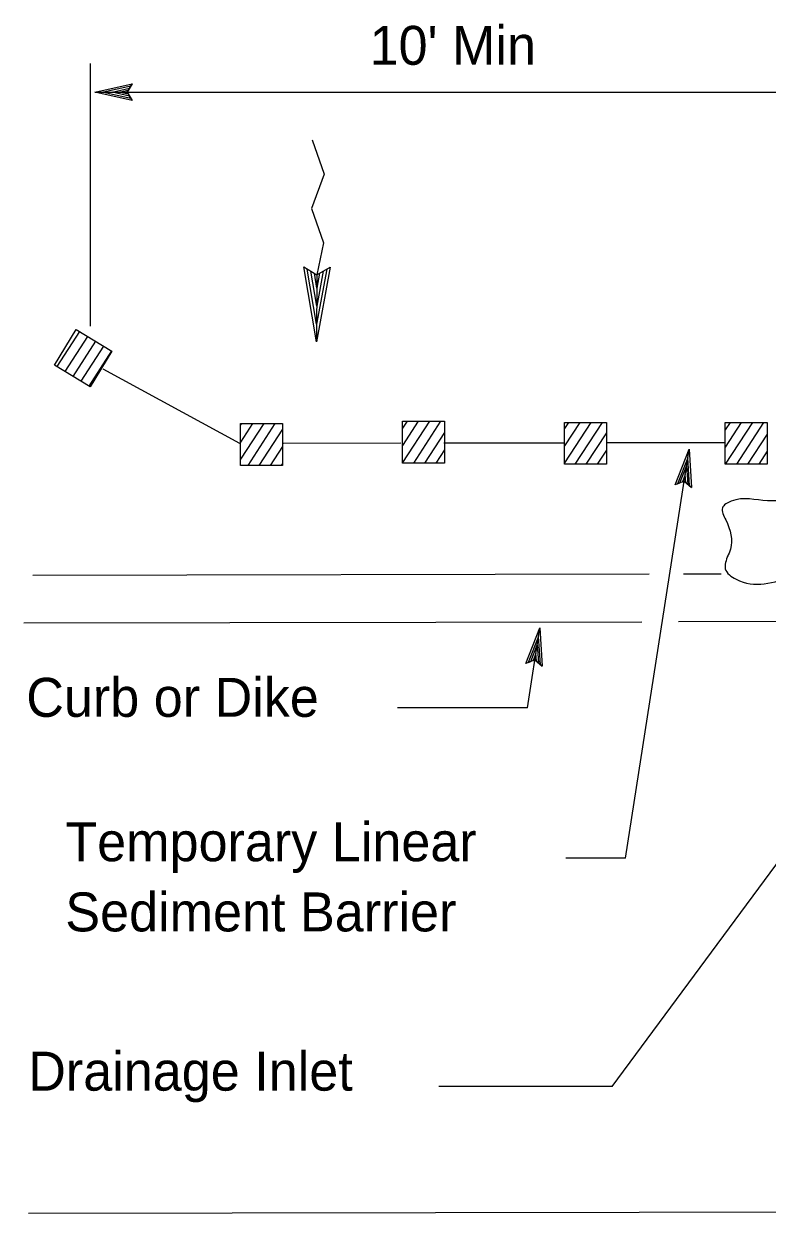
# Model space of a CAD drawing. Extents: x 6708945 to 6710368, y 1871409 to 1872338.
# Drawn here: x 6709577.4 to 6709691.9, y 1871532.3 to 1871715.4 of the extents above; entities that cross this region are included whole.
import ezdxf

# ---------------------------------------------------------------- set-up
doc = ezdxf.new("R2010")
doc.units = 0
for name, color, linetype in [('1 Control', 7, 'Continuous'), ('57 Undefined', 7, 'Continuous'), ('60 Nongeo Data', 7, 'Continuous'), ('63 Undefined', 7, 'Continuous')]:
    doc.layers.add(name, color=color, linetype=linetype)

msp = doc.modelspace()

# ---------------------------------------------------------------- linework, layer by layer
at = {"layer": '1 Control'}
for p, q in [((6709586, 1871668.01), (6709582.49, 1871662.61)), ((6709587.23, 1871667.27), (6709583.72, 1871661.86)), ((6709588.46, 1871666.52), (6709584.95, 1871661.12)), ((6709589.69, 1871665.77), (6709586.18, 1871660.37)), ((6709590.92, 1871665.03), (6709587.42, 1871659.62)), ((6709614.35, 1871653.84), (6709610.79, 1871648.35)), ((6709612.63, 1871653.84), (6709610.79, 1871650.99)), ((6709610.92, 1871653.84), (6709610.79, 1871653.64)), ((6709616.07, 1871653.84), (6709611.89, 1871647.4)), ((6709639.86, 1871654.22), (6709635.72, 1871647.85)), ((6709638.14, 1871654.22), (6709635.72, 1871650.5)), ((6709636.43, 1871654.22), (6709635.72, 1871653.14)), ((6709641.58, 1871654.22), (6709637.4, 1871647.78)), ((6709664.71, 1871654.03), (6709660.66, 1871647.8)), ((6709662.99, 1871654.03), (6709660.66, 1871650.44)), ((6709661.28, 1871654.03), (6709660.66, 1871653.09)), ((6709666.43, 1871654.03), (6709662.25, 1871647.59)), ((6709689.59, 1871654.03), (6709685.41, 1871647.6)), ((6709687.87, 1871654.03), (6709685.41, 1871650.24)), ((6709686.16, 1871654.03), (6709685.41, 1871652.89)), ((6709691.31, 1871654.03), (6709687.12, 1871647.59)), ((6709617.22, 1871652.97), (6709613.6, 1871647.4)), ((6709642.16, 1871652.47), (6709639.11, 1871647.78)), ((6709667.1, 1871652.42), (6709663.96, 1871647.59)), ((6709691.85, 1871652.22), (6709688.84, 1871647.59)), ((6709617.22, 1871650.33), (6709615.32, 1871647.4)), ((6709642.16, 1871649.83), (6709640.83, 1871647.78)), ((6709667.1, 1871649.78), (6709665.68, 1871647.59)), ((6709691.85, 1871649.58), (6709690.56, 1871647.59)), ((6709617.22, 1871647.69), (6709617.04, 1871647.4))]:
    msp.add_line(p, q, dxfattribs=at)
for points in [[(6709585.47, 1871668.33), (6709590.98, 1871664.99), (6709587.64, 1871659.49), (6709582.14, 1871662.83)], [(6709610.79, 1871653.84), (6709617.22, 1871653.84), (6709617.22, 1871647.4), (6709610.79, 1871647.4)], [(6709635.72, 1871654.22), (6709642.16, 1871654.22), (6709642.16, 1871647.78), (6709635.72, 1871647.78)], [(6709660.66, 1871654.03), (6709667.1, 1871654.03), (6709667.1, 1871647.59), (6709660.66, 1871647.59)], [(6709685.41, 1871654.03), (6709691.85, 1871654.03), (6709691.85, 1871647.59), (6709685.41, 1871647.59)]]:
    msp.add_lwpolyline(points, close=True, dxfattribs=at)
at = {"layer": '57 Undefined'}
for p, q in [((6709587.7, 1871668.85), (6709587.7, 1871709.29)), ((6709588.34, 1871704.86), (6709715.63, 1871704.86)), ((6709670.02, 1871586.95), (6709679.85, 1871649.92)), ((6709654.95, 1871610.12), (6709656.87, 1871622.41)), ((6709654.95, 1871610.12), (6709634.94, 1871610.12)), ((6709668.01, 1871551.82), (6709699.53, 1871594.51)), ((6709670.02, 1871586.95), (6709660.85, 1871586.95)), ((6709668.01, 1871551.82), (6709641.29, 1871551.82))]:
    msp.add_line(p, q, dxfattribs=at)
at = {"layer": '60 Nongeo Data'}
for p, q in [((6709594.1, 1871706.14), (6709594.1, 1871706.14)), ((6709588.34, 1871704.86), (6709588.34, 1871704.86)), ((6709594.1, 1871703.58), (6709594.1, 1871703.58)), ((6709679.85, 1871649.92), (6709679.85, 1871649.92)), ((6709677.69, 1871644.43), (6709677.69, 1871644.43)), ((6709680.22, 1871644.03), (6709680.22, 1871644.03)), ((6709656.87, 1871622.41), (6709656.87, 1871622.41)), ((6709654.71, 1871616.91), (6709654.71, 1871616.91)), ((6709657.24, 1871616.52), (6709657.24, 1871616.52))]:
    msp.add_line(p, q, dxfattribs=at)
for points in [[(6709594.1, 1871703.58), (6709588.34, 1871704.86), (6709594.1, 1871706.14), (6709593.9, 1871705.8), (6709589.68, 1871704.87), (6709593.9, 1871703.92), (6709593.7, 1871704.26), (6709591, 1871704.86), (6709593.69, 1871705.46), (6709593.49, 1871705.12), (6709592.32, 1871704.86), (6709593.49, 1871704.6), (6709593.34, 1871704.86), (6709594.1, 1871706.14), (6709593.34, 1871704.86)], [(6709677.69, 1871644.43), (6709679.85, 1871649.92), (6709680.22, 1871644.03), (6709679.92, 1871644.29), (6709679.65, 1871648.6), (6709678.06, 1871644.58), (6709678.43, 1871644.73), (6709679.44, 1871647.3), (6709679.62, 1871644.54), (6709679.31, 1871644.8), (6709679.23, 1871645.99), (6709678.8, 1871644.88), (6709679.08, 1871644.99), (6709680.22, 1871644.03), (6709679.08, 1871644.99)], [(6709654.71, 1871616.91), (6709656.87, 1871622.41), (6709657.24, 1871616.52), (6709656.94, 1871616.77), (6709656.67, 1871621.09), (6709655.08, 1871617.06), (6709655.45, 1871617.21), (6709656.46, 1871619.79), (6709656.63, 1871617.03), (6709656.33, 1871617.28), (6709656.25, 1871618.48), (6709655.82, 1871617.36), (6709656.1, 1871617.47), (6709657.24, 1871616.52), (6709656.1, 1871617.47)]]:
    msp.add_lwpolyline(points, close=True, dxfattribs=at)
for points in [[(6709589.56, 1871662.27), (6709610.62, 1871650.83)], [(6709617.38, 1871650.84), (6709635.47, 1871650.87)], [(6709642.09, 1871650.88), (6709660.59, 1871650.91)], [(6709667.08, 1871650.92), (6709685.38, 1871650.95)], [(6709578.82, 1871630.54), (6709673.67, 1871630.7)], [(6709678.95, 1871630.71), (6709684.77, 1871630.72)], [(6709577.41, 1871623.19), (6709672.55, 1871623.35)], [(6709678.2, 1871623.36), (6709932.4, 1871623.77)], [(6709578.14, 1871532.3), (6710048.25, 1871533.08)]]:
    msp.add_lwpolyline(points, dxfattribs=at)
msp.add_spline([(6709685.81, 1871633.55), (6709685.41, 1871631.49), (6709687.07, 1871629.88), (6709695.81, 1871630.27), (6709699.39, 1871631.08), (6709704.17, 1871630.12), (6709708.12, 1871629.94), (6709708.74, 1871631.23), (6709709.2, 1871640.9), (6709707.25, 1871644.03), (6709703.6, 1871644.06), (6709697.36, 1871642.67), (6709691.88, 1871641.95), (6709686.33, 1871641.92), (6709684.96, 1871640.86), (6709685.47, 1871639.03), (6709686.2, 1871634.53), (6709685.73, 1871633.32)], degree=3, dxfattribs=at)
at = {"layer": '63 Undefined'}
for p, q in [((6709622.46, 1871666.41), (6709620.53, 1871677.97)), ((6709620.53, 1871677.97), (6709622.55, 1871676.77)), ((6709622.48, 1871669.17), (6709621.06, 1871677.64)), ((6709624.6, 1871677.93), (6709622.46, 1871666.41)), ((6709624.06, 1871677.62), (6709622.48, 1871669.17)), ((6709622.55, 1871676.77), (6709624.6, 1871677.93)), ((6709622.51, 1871671.9), (6709621.61, 1871677.32)), ((6709622.54, 1871674.71), (6709622.15, 1871677)), ((6709623.51, 1871677.3), (6709622.51, 1871671.9)), ((6709622.96, 1871676.99), (6709622.54, 1871674.71))]:
    msp.add_line(p, q, dxfattribs=at)
msp.add_lwpolyline([(6709621.79, 1871697.54), (6709623.65, 1871692.24), (6709621.7, 1871686.98), (6709623.55, 1871681.67), (6709622.55, 1871676.77), (6709622.46, 1871666.41)], dxfattribs=at)

# ---------------------------------------------------------------- texts
at = {"layer": '57 Undefined'}
for s, p in [("10' Min", (6709630.65, 1871709.07)), ('Curb or Dike', (6709577.8, 1871608.71)), ('Temporary Linear', (6709583.81, 1871586.48)), ('Sediment Barrier', (6709583.81, 1871575.68)), ('Drainage Inlet', (6709578.1, 1871551.17))]:
    msp.add_text(s, height=6, dxfattribs=at).set_placement(p)

doc.saveas('drawing.dxf')
